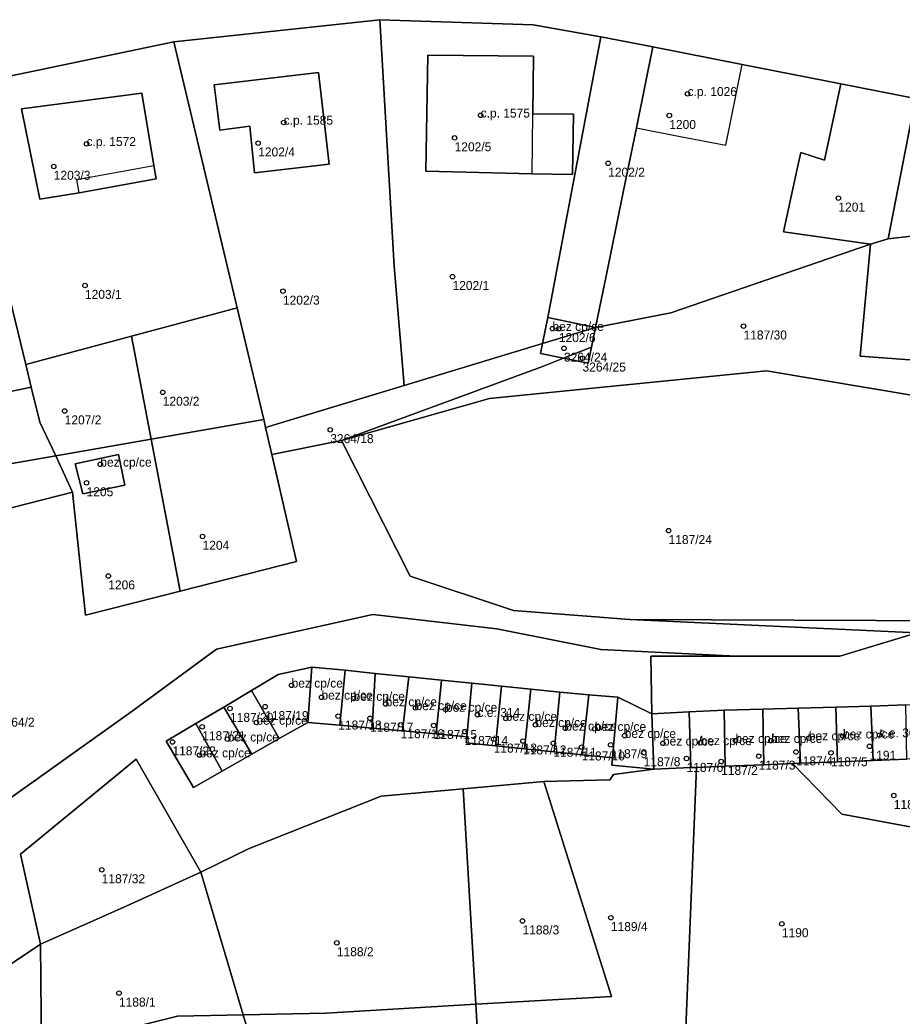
# Model space of a CAD drawing. Extents: x -878211 to -870363, y -1058464 to -1052522.
# Drawn here: x -875506.9 to -875408.6, y -1056330.6 to -1056219.6 of the extents above; entities that cross this region are included whole.
import ezdxf

# ---------------------------------------------------------------- set-up
doc = ezdxf.new("R2010")
doc.units = 0
for name, color, linetype in [('Definiční body', 7, 'Continuous'), ('Polygon budovy', 7, 'Continuous'), ('Polygon parcely', 7, 'Continuous')]:
    doc.layers.add(name, color=color, linetype=linetype)

msp = doc.modelspace()

# ---------------------------------------------------------------- linework, layer by layer
at = {"layer": 'Definiční body'}
for centre in [(-875432.53, -1056227.81994), (-875455.6, -1056230.21994), (-875434.57, -1056230.24994), (-875477.55, -1056231.01994), (-875458.5, -1056232.73994), (-875499.52, -1056233.39994), (-875480.39, -1056233.31994), (-875503.18, -1056235.91994), (-875441.38, -1056235.56994), (-875415.72, -1056239.45994), (-875458.73, -1056248.19994), (-875499.7, -1056249.18994), (-875477.63, -1056249.82994), (-875447.59, -1056253.99994), (-875446.88, -1056254.00994), (-875426.29, -1056253.71994), (-875446.31, -1056256.18994), (-875444.24, -1056257.28994), (-875491.03, -1056261.09994), (-875501.96, -1056263.17994), (-875472.36, -1056265.26994), (-875497.99, -1056269.12994), (-875499.52, -1056271.18994), (-875486.59, -1056277.15994), (-875434.65, -1056276.51994), (-875497.1, -1056281.56994), (-875476.67, -1056293.75994), (-875473.34, -1056295.09994), (-875469.76, -1056295.22994), (-875483.53, -1056296.33994), (-875479.61, -1056296.13994), (-875466.19, -1056295.83994), (-875462.86, -1056296.26994), (-875471.47, -1056297.18994), (-875467.93, -1056297.43994), (-875459.47, -1056296.44994), (-875455.95, -1056297.02994), (-875452.8, -1056297.45994), (-875486.63, -1056298.37994), (-875480.59, -1056297.89994), (-875464.51, -1056298.15994), (-875460.83, -1056298.23994), (-875449.49, -1056298.14994), (-875446.15, -1056298.54994), (-875457.37, -1056298.91994), (-875442.87, -1056298.59994), (-875439.54, -1056299.36994), (-875419.02, -1056299.63994), (-875415.21, -1056299.42994), (-875411.13, -1056299.29994), (-875489.95, -1056300.06994), (-875483.81, -1056299.75994), (-875454.15, -1056299.75994), (-875450.87, -1056299.96994), (-875447.49, -1056300.21994), (-875444.34, -1056300.63994), (-875441.1, -1056300.38994), (-875435.28, -1056300.21994), (-875431.09, -1056300.16994), (-875427.2, -1056299.92994), (-875423.23, -1056299.92994), (-875412.25, -1056300.55994), (-875486.94, -1056301.52994), (-875437.42, -1056301.27994), (-875432.65, -1056301.90994), (-875424.6, -1056301.65994), (-875420.44, -1056301.18994), (-875416.55, -1056301.27994), (-875428.79, -1056302.24994), (-875409.55, -1056306.03994), (-875497.83, -1056314.31994), (-875441.08, -1056319.65994), (-875450.93, -1056320.02994), (-875422.02, -1056320.33994), (-875471.62, -1056322.45994), (-875495.91, -1056328.06994)]:
    msp.add_circle(centre, 0.25, dxfattribs=at)
at = {"layer": 'Polygon budovy'}
for points in [[(-875436.42, -1056222.58), (-875438.21, -1056231.61), (-875433.35, -1056232.59), (-875428.26, -1056233.56), (-875426.44, -1056224.56)], [(-875461.48, -1056223.5), (-875461.69, -1056236.43), (-875449.85, -1056236.74), (-875449.78, -1056230.05), (-875449.69, -1056223.64)], [(-875473.68, -1056225.46), (-875485.3, -1056226.82), (-875484.66, -1056231.86), (-875481.33, -1056231.45), (-875480.82, -1056236.64), (-875472.49, -1056235.68)], [(-875493.38, -1056227.76), (-875506.77, -1056229.51), (-875504.74, -1056239.58), (-875500.36, -1056238.86), (-875500.61, -1056237.36), (-875492.01, -1056235.82)], [(-875448.94, -1056256.76), (-875446.37, -1056257.29), (-875443.61, -1056257.86), (-875443.23, -1056256.05), (-875442.78, -1056253.86), (-875448.11, -1056252.74), (-875448.71, -1056255.66)], [(-875495.98, -1056268.04), (-875500.78, -1056269.05), (-875499.95, -1056272.42), (-875495.27, -1056271.43)], [(-875478.16, -1056292.55), (-875481.15, -1056294.33), (-875478.04, -1056299.69), (-875474.86, -1056297.88), (-875474.42, -1056291.72)], [(-875474.42, -1056291.72), (-875474.86, -1056297.88), (-875471.31, -1056298.2), (-875470.69, -1056292.07)], [(-875467.67, -1056298.53), (-875467.34, -1056292.43), (-875470.69, -1056292.07), (-875471.31, -1056298.2)], [(-875467.67, -1056298.53), (-875464.31, -1056298.83), (-875463.59, -1056292.81), (-875467.34, -1056292.43)], [(-875464.31, -1056298.83), (-875460.57, -1056299.17), (-875459.97, -1056293.18), (-875463.59, -1056292.81)], [(-875460.57, -1056299.17), (-875457.15, -1056299.48), (-875456.58, -1056293.51), (-875459.97, -1056293.18)], [(-875457.15, -1056299.48), (-875457.21, -1056300.18), (-875453.95, -1056300.51), (-875453.27, -1056293.85), (-875456.58, -1056293.51)], [(-875453.27, -1056293.85), (-875453.95, -1056300.51), (-875450.69, -1056300.85), (-875450.02, -1056294.2)], [(-875481.15, -1056294.33), (-875484.23, -1056296.19), (-875481.1, -1056301.44), (-875478.04, -1056299.69)], [(-875450.02, -1056294.2), (-875450.69, -1056300.85), (-875447.42, -1056301.18), (-875446.78, -1056294.5)], [(-875446.78, -1056294.5), (-875447.42, -1056301.18), (-875444.28, -1056301.5), (-875443.54, -1056294.8)], [(-875444.28, -1056301.5), (-875440.9, -1056301.84), (-875440.3, -1056295.09), (-875443.54, -1056294.8)], [(-875440.98, -1056302.65), (-875436.29, -1056303.09), (-875436.52, -1056296.94), (-875440.3, -1056295.09), (-875440.9, -1056301.84)], [(-875412.12, -1056296.06), (-875416.02, -1056296.19), (-875415.81, -1056302.28), (-875411.83, -1056302.12)], [(-875408.21, -1056295.93), (-875412.12, -1056296.06), (-875411.83, -1056302.12), (-875408.09, -1056301.98)], [(-875484.23, -1056296.19), (-875487.35, -1056298.02), (-875484.41, -1056303.32), (-875481.1, -1056301.44)], [(-875432.35, -1056296.72), (-875436.52, -1056296.94), (-875436.29, -1056303.09), (-875432.16, -1056302.93)], [(-875428.45, -1056296.53), (-875432.35, -1056296.72), (-875432.16, -1056302.93), (-875431.52, -1056302.9), (-875428.34, -1056302.78)], [(-875424.13, -1056296.4), (-875428.45, -1056296.53), (-875428.34, -1056302.78), (-875424.03, -1056302.61)], [(-875420.2, -1056296.3), (-875424.13, -1056296.4), (-875424.03, -1056302.61), (-875420.85, -1056302.48), (-875419.95, -1056302.44)], [(-875416.02, -1056296.19), (-875420.2, -1056296.3), (-875419.95, -1056302.44), (-875415.81, -1056302.28)], [(-875487.35, -1056298.02), (-875490.64, -1056299.99), (-875487.59, -1056305.13), (-875484.41, -1056303.32)]]:
    msp.add_lwpolyline(points, close=True, dxfattribs=at)
at = {"layer": 'Polygon parcely'}
for points in [[(-875611.38, -1056250.03), (-875591.34, -1056245.14), (-875577.58, -1056242.07), (-875562.16, -1056239.29), (-875547.53, -1056235.13), (-875540.74, -1056233.15), (-875537.65, -1056232.55), (-875513.82, -1056227.05), (-875489.8, -1056222.05), (-875466.82, -1056219.59), (-875449.74, -1056220.14), (-875442.2, -1056221.48), (-875436.42, -1056222.58), (-875426.44, -1056224.56), (-875415.46, -1056226.72), (-875407.14, -1056228.36)], [(-875509.54, -1056307.36), (-875494.44, -1056296.62), (-875485.04, -1056289.72), (-875467.61, -1056285.87), (-875453.79, -1056287.46), (-875442.19, -1056289.75), (-875427.13, -1056290.52), (-875415.57, -1056290.51), (-875406.97, -1056287.91), (-875438.96, -1056286.41), (-875451.95, -1056285.4), (-875463.46, -1056281.58), (-875467.91, -1056272.8), (-875471.12, -1056266.48), (-875478.86, -1056268.03), (-875476.11, -1056279.94), (-875489.08, -1056283.25), (-875499.63, -1056285.94), (-875501.1, -1056272.24), (-875519.13, -1056276.83)], [(-875521.41, -1056333.83), (-875504.67, -1056322.59), (-875506.9, -1056312.58), (-875494.01, -1056301.99), (-875486.78, -1056314.58), (-875481.41, -1056311.93), (-875466.7, -1056306.12), (-875457.54, -1056305.3), (-875448.56, -1056304.49), (-875441.2, -1056304.28), (-875440.8, -1056303.7), (-875436.29, -1056303.09), (-875440.98, -1056302.65), (-875440.9, -1056301.84), (-875444.28, -1056301.5), (-875447.42, -1056301.18), (-875450.69, -1056300.85), (-875453.95, -1056300.51), (-875457.21, -1056300.18), (-875457.15, -1056299.48), (-875460.57, -1056299.17), (-875464.31, -1056298.83), (-875467.67, -1056298.53), (-875471.31, -1056298.2), (-875474.86, -1056297.88), (-875478.04, -1056299.69), (-875481.1, -1056301.44), (-875484.41, -1056303.32), (-875487.59, -1056305.13), (-875490.64, -1056299.99), (-875487.35, -1056298.02), (-875484.23, -1056296.19), (-875481.15, -1056294.33), (-875478.16, -1056292.55), (-875474.42, -1056291.72), (-875470.69, -1056292.07), (-875467.34, -1056292.43), (-875463.59, -1056292.81), (-875459.97, -1056293.18), (-875456.58, -1056293.51), (-875453.27, -1056293.85), (-875450.02, -1056294.2), (-875446.78, -1056294.5), (-875443.54, -1056294.8), (-875440.3, -1056295.09), (-875436.52, -1056296.94), (-875436.64, -1056290.52), (-875427.13, -1056290.52), (-875442.19, -1056289.75), (-875453.79, -1056287.46), (-875467.61, -1056285.87), (-875485.04, -1056289.72), (-875494.44, -1056296.62), (-875509.54, -1056307.36)]]:
    msp.add_lwpolyline(points, dxfattribs=at)
for points in [[(-875466.82, -1056219.59), (-875489.8, -1056222.05), (-875482.73, -1056251.69), (-875479.76, -1056264.14), (-875479.56, -1056265.02), (-875464.13, -1056260.34), (-875465.22, -1056247.05)], [(-875449.74, -1056220.14), (-875466.82, -1056219.59), (-875465.22, -1056247.05), (-875464.13, -1056260.34), (-875448.71, -1056255.66), (-875448.11, -1056252.74), (-875442.2, -1056221.48)], [(-875442.78, -1056253.86), (-875441.71, -1056248.68), (-875441.1, -1056245.6), (-875439.71, -1056238.79), (-875438.21, -1056231.61), (-875436.42, -1056222.58), (-875442.2, -1056221.48), (-875448.11, -1056252.74)], [(-875506.3, -1056258), (-875494.52, -1056254.85), (-875482.73, -1056251.69), (-875489.8, -1056222.05), (-875513.82, -1056227.05)], [(-875436.42, -1056222.58), (-875438.21, -1056231.61), (-875439.71, -1056238.79), (-875441.1, -1056245.6), (-875441.71, -1056248.68), (-875442.78, -1056253.86), (-875434.41, -1056252.24), (-875412.13, -1056244.58), (-875421.83, -1056243.21), (-875420.25, -1056235.85), (-875419.92, -1056234.36), (-875417.28, -1056235.22), (-875415.46, -1056226.72), (-875426.44, -1056224.56)], [(-875445.25, -1056230.11), (-875449.78, -1056230.05), (-875449.69, -1056223.64), (-875461.48, -1056223.5), (-875461.69, -1056236.43), (-875449.85, -1056236.74), (-875445.34, -1056236.82)], [(-875445.25, -1056230.11), (-875445.34, -1056236.82), (-875449.85, -1056236.74), (-875461.69, -1056236.43), (-875461.48, -1056223.5), (-875449.69, -1056223.64), (-875449.78, -1056230.05)], [(-875481.33, -1056231.45), (-875480.82, -1056236.64), (-875472.49, -1056235.68), (-875473.68, -1056225.46), (-875485.3, -1056226.82), (-875484.66, -1056231.86)], [(-875481.33, -1056231.45), (-875484.66, -1056231.86), (-875485.3, -1056226.82), (-875473.68, -1056225.46), (-875472.49, -1056235.68), (-875480.82, -1056236.64)], [(-875506.3, -1056258), (-875513.82, -1056227.05), (-875537.65, -1056232.55), (-875533.04, -1056249.41), (-875532.94, -1056249.39), (-875536.29, -1056235.81), (-875526.24, -1056233.49), (-875525.61, -1056236.17), (-875523.04, -1056247.06), (-875532.75, -1056249.33), (-875531.19, -1056254.59), (-875531.52, -1056254.69), (-875528.65, -1056265.31), (-875505.68, -1056260.52)], [(-875415.46, -1056226.72), (-875417.28, -1056235.22), (-875419.92, -1056234.36), (-875420.25, -1056235.85), (-875421.83, -1056243.21), (-875412.13, -1056244.58), (-875410.18, -1056244), (-875407.14, -1056228.36)], [(-875500.36, -1056238.86), (-875491.76, -1056237.29), (-875492.01, -1056235.82), (-875493.38, -1056227.76), (-875506.77, -1056229.51), (-875504.74, -1056239.58)], [(-875500.36, -1056238.86), (-875504.74, -1056239.58), (-875506.77, -1056229.51), (-875493.38, -1056227.76), (-875492.01, -1056235.82), (-875491.76, -1056237.29)], [(-875392.29, -1056241.93), (-875390.52, -1056233.36), (-875390.16, -1056231.64), (-875407.14, -1056228.36), (-875410.18, -1056244)], [(-875381.72, -1056233.32), (-875383.35, -1056241.37), (-875383.81, -1056243.65), (-875386.56, -1056243.09), (-875392.29, -1056241.93), (-875410.18, -1056244), (-875412.13, -1056244.58), (-875413.29, -1056257.08), (-875402.24, -1056257.89), (-875401.83, -1056253.97), (-875395.92, -1056254.53), (-875396.34, -1056258.51), (-875381.73, -1056259.45), (-875373.92, -1056234.86)], [(-875471.12, -1056266.48), (-875454.6, -1056261.79), (-875423.74, -1056258.7), (-875395.61, -1056263.42), (-875385.95, -1056267.35), (-875386.1, -1056272.7), (-875381.73, -1056259.45), (-875396.34, -1056258.51), (-875402.24, -1056257.89), (-875413.29, -1056257.08), (-875412.13, -1056244.58), (-875434.41, -1056252.24), (-875442.78, -1056253.86), (-875443.23, -1056256.05), (-875443.61, -1056257.86), (-875446.37, -1056257.29), (-875448.58, -1056258.17)], [(-875492.32, -1056266.32), (-875479.76, -1056264.14), (-875482.73, -1056251.69), (-875494.52, -1056254.85)], [(-875442.78, -1056253.86), (-875448.11, -1056252.74), (-875448.71, -1056255.66)], [(-875443.23, -1056256.05), (-875442.78, -1056253.86), (-875448.71, -1056255.66), (-875448.94, -1056256.76), (-875446.37, -1056257.29)], [(-875526.64, -1056273.08), (-875520.69, -1056271.27), (-875502.95, -1056268.17), (-875504.74, -1056264.41), (-875505.68, -1056260.52), (-875528.65, -1056265.31), (-875531.52, -1056254.69), (-875534.6, -1056255.61), (-875532.63, -1056264.23), (-875529.8, -1056273.48)], [(-875505.68, -1056260.52), (-875504.74, -1056264.41), (-875502.95, -1056268.17), (-875492.32, -1056266.32), (-875494.52, -1056254.85), (-875506.3, -1056258)], [(-875478.86, -1056268.03), (-875471.12, -1056266.48), (-875448.58, -1056258.17), (-875446.37, -1056257.29), (-875448.94, -1056256.76), (-875448.71, -1056255.66), (-875464.13, -1056260.34), (-875479.56, -1056265.02)], [(-875446.37, -1056257.29), (-875443.61, -1056257.86), (-875443.23, -1056256.05)], [(-875395.61, -1056263.42), (-875423.74, -1056258.7), (-875454.6, -1056261.79), (-875471.12, -1056266.48), (-875467.91, -1056272.8), (-875463.46, -1056281.58), (-875451.95, -1056285.4), (-875438.96, -1056286.41), (-875402.38, -1056286.56), (-875390.47, -1056273.64), (-875392.98, -1056269.66)], [(-875492.32, -1056266.32), (-875489.08, -1056283.25), (-875476.11, -1056279.94), (-875478.86, -1056268.03), (-875479.56, -1056265.02), (-875479.76, -1056264.14)], [(-875502.95, -1056268.17), (-875501.1, -1056272.24), (-875499.63, -1056285.94), (-875489.08, -1056283.25), (-875492.32, -1056266.32)], [(-875519.39, -1056275.83), (-875522.49, -1056276.71), (-875522.73, -1056275.56), (-875524.7, -1056276.1), (-875525.38, -1056273.71), (-875526.36, -1056273.99), (-875526.64, -1056273.08), (-875529.8, -1056273.48), (-875537.28, -1056275.95), (-875535.63, -1056281.06), (-875535, -1056283.13), (-875526.21, -1056281.22), (-875525.41, -1056281.05), (-875525.43, -1056278.43), (-875519.13, -1056276.83), (-875501.1, -1056272.24), (-875502.95, -1056268.17), (-875520.69, -1056271.27), (-875519.6, -1056274.64)], [(-875495.27, -1056271.43), (-875499.95, -1056272.42), (-875500.78, -1056269.05), (-875495.98, -1056268.04)], [(-875495.27, -1056271.43), (-875495.98, -1056268.04), (-875500.78, -1056269.05), (-875499.95, -1056272.42)], [(-875438.96, -1056286.41), (-875406.97, -1056287.91), (-875394.57, -1056286.98), (-875391.02, -1056285.88), (-875386.1, -1056272.7), (-875402.38, -1056286.56)], [(-875404.17, -1056295.75), (-875400.44, -1056295.61), (-875396.44, -1056295.47), (-875396.26, -1056301.51), (-875391.02, -1056285.88), (-875394.57, -1056286.98), (-875406.97, -1056287.91), (-875415.57, -1056290.51), (-875427.13, -1056290.52), (-875436.64, -1056290.52), (-875436.52, -1056296.94), (-875432.35, -1056296.72), (-875428.45, -1056296.53), (-875424.13, -1056296.4), (-875420.2, -1056296.3), (-875416.02, -1056296.19), (-875412.12, -1056296.06), (-875408.21, -1056295.93)], [(-875478.04, -1056299.69), (-875474.86, -1056297.88), (-875474.42, -1056291.72), (-875478.16, -1056292.55), (-875481.15, -1056294.33)], [(-875474.86, -1056297.88), (-875471.31, -1056298.2), (-875470.69, -1056292.07), (-875474.42, -1056291.72)], [(-875470.69, -1056292.07), (-875471.31, -1056298.2), (-875467.67, -1056298.53), (-875467.34, -1056292.43)], [(-875467.34, -1056292.43), (-875467.67, -1056298.53), (-875464.31, -1056298.83), (-875463.59, -1056292.81)], [(-875463.59, -1056292.81), (-875464.31, -1056298.83), (-875460.57, -1056299.17), (-875459.97, -1056293.18)], [(-875459.97, -1056293.18), (-875460.57, -1056299.17), (-875457.15, -1056299.48), (-875456.58, -1056293.51)], [(-875457.15, -1056299.48), (-875457.21, -1056300.18), (-875453.95, -1056300.51), (-875453.27, -1056293.85), (-875456.58, -1056293.51)], [(-875453.95, -1056300.51), (-875450.69, -1056300.85), (-875450.02, -1056294.2), (-875453.27, -1056293.85)], [(-875481.1, -1056301.44), (-875478.04, -1056299.69), (-875481.15, -1056294.33), (-875484.23, -1056296.19)], [(-875450.69, -1056300.85), (-875447.42, -1056301.18), (-875446.78, -1056294.5), (-875450.02, -1056294.2)], [(-875447.42, -1056301.18), (-875444.28, -1056301.5), (-875443.54, -1056294.8), (-875446.78, -1056294.5)], [(-875443.54, -1056294.8), (-875444.28, -1056301.5), (-875440.9, -1056301.84), (-875440.3, -1056295.09)], [(-875440.3, -1056295.09), (-875440.9, -1056301.84), (-875440.98, -1056302.65), (-875436.29, -1056303.09), (-875436.52, -1056296.94)], [(-875412.12, -1056296.06), (-875416.02, -1056296.19), (-875415.81, -1056302.28), (-875411.83, -1056302.12)], [(-875408.21, -1056295.93), (-875412.12, -1056296.06), (-875411.83, -1056302.12), (-875408.09, -1056301.98)], [(-875487.35, -1056298.02), (-875484.41, -1056303.32), (-875481.1, -1056301.44), (-875484.23, -1056296.19)], [(-875436.29, -1056303.09), (-875432.16, -1056302.93), (-875432.35, -1056296.72), (-875436.52, -1056296.94)], [(-875432.35, -1056296.72), (-875432.16, -1056302.93), (-875431.52, -1056302.9), (-875428.34, -1056302.78), (-875428.45, -1056296.53)], [(-875424.13, -1056296.4), (-875428.45, -1056296.53), (-875428.34, -1056302.78), (-875424.03, -1056302.61)], [(-875420.2, -1056296.3), (-875424.13, -1056296.4), (-875424.03, -1056302.61), (-875420.85, -1056302.48), (-875419.95, -1056302.44)], [(-875416.02, -1056296.19), (-875420.2, -1056296.3), (-875419.95, -1056302.44), (-875415.81, -1056302.28)], [(-875487.35, -1056298.02), (-875490.64, -1056299.99), (-875487.59, -1056305.13), (-875484.41, -1056303.32)], [(-875411.83, -1056302.12), (-875415.81, -1056302.28), (-875419.95, -1056302.44), (-875420.85, -1056302.48), (-875415.33, -1056308.13), (-875403.11, -1056310.38), (-875400.67, -1056314.05), (-875396.26, -1056301.51), (-875400.2, -1056301.67), (-875403.75, -1056301.81), (-875408.09, -1056301.98)], [(-875504.67, -1056322.59), (-875495.44, -1056318.53), (-875486.78, -1056314.58), (-875494.01, -1056301.99), (-875506.9, -1056312.58)], [(-875418.39, -1056347.04), (-875414.86, -1056347.4), (-875411.47, -1056347.74), (-875411.16, -1056348.42), (-875410.64, -1056347.42), (-875406.59, -1056333.71), (-875400.67, -1056314.05), (-875403.11, -1056310.38), (-875415.33, -1056308.13), (-875420.85, -1056302.48), (-875424.03, -1056302.61), (-875428.34, -1056302.78), (-875431.52, -1056302.9), (-875433.3, -1056345.53)], [(-875449.57, -1056343.88), (-875439.97, -1056344.85), (-875436.47, -1056345.21), (-875433.3, -1056345.53), (-875431.52, -1056302.9), (-875432.16, -1056302.93), (-875436.29, -1056303.09), (-875440.8, -1056303.7), (-875441.2, -1056304.28), (-875448.56, -1056304.49), (-875441.02, -1056328.43), (-875456.13, -1056329.31), (-875455.26, -1056344.25)], [(-875441.02, -1056328.43), (-875448.56, -1056304.49), (-875457.54, -1056305.3), (-875456.13, -1056329.31)], [(-875456.13, -1056329.31), (-875457.54, -1056305.3), (-875466.7, -1056306.12), (-875481.41, -1056311.93), (-875486.78, -1056314.58), (-875482.06, -1056330.48), (-875472.81, -1056330.29)], [(-875504.67, -1056322.59), (-875504.56, -1056334.43), (-875489.37, -1056330.63), (-875482.06, -1056330.48), (-875486.78, -1056314.58), (-875495.44, -1056318.53)], [(-875565.35, -1056373.86), (-875555.26, -1056383.73), (-875541.31, -1056375.12), (-875531.82, -1056371.99), (-875520.61, -1056369.18), (-875525.82, -1056349.47), (-875501.96, -1056342.97), (-875503.24, -1056337.88), (-875504.56, -1056334.43), (-875504.67, -1056322.59), (-875521.41, -1056333.83), (-875540.21, -1056349.03)], [(-875478.72, -1056339.14), (-875474.96, -1056338.03), (-875472.87, -1056345.69), (-875472.64, -1056346.14), (-875472.33, -1056345.99), (-875469.56, -1056345.17), (-875460.75, -1056344.6), (-875457.31, -1056344.38), (-875455.26, -1056344.25), (-875456.13, -1056329.31), (-875472.81, -1056330.29), (-875482.06, -1056330.48), (-875479.42, -1056339.35)], [(-875477.91, -1056347.65), (-875477.65, -1056346.14), (-875477.86, -1056344.63), (-875479.42, -1056339.35), (-875482.06, -1056330.48), (-875489.37, -1056330.63), (-875504.56, -1056334.43), (-875503.24, -1056337.88), (-875501.96, -1056342.97), (-875498.26, -1056353.69), (-875482.41, -1056348.99), (-875478.17, -1056347.73)]]:
    msp.add_lwpolyline(points, close=True, dxfattribs=at)

# ---------------------------------------------------------------- texts
at = {"layer": 'Definiční body'}
for s, p in [('c.p. 1026', (-875432.53, -1056228.07)), ('c.p. 1575', (-875455.6, -1056230.47)), ('c.p. 1585', (-875477.55, -1056231.27)), ('1200', (-875434.57, -1056231.739)), ('c.p. 1572', (-875499.52, -1056233.649)), ('1202/4', (-875480.39, -1056234.809)), ('1202/5', (-875458.5, -1056234.229)), ('1202/2', (-875441.38, -1056237.059)), ('1203/3', (-875503.18, -1056237.409)), ('1201', (-875415.72, -1056240.949)), ('1202/1', (-875458.73, -1056249.689)), ('1203/1', (-875499.7, -1056250.679)), ('1202/3', (-875477.63, -1056251.319)), ('bez cp/ce', (-875447.59, -1056254.25)), ('1202/6', (-875446.88, -1056255.499)), ('1187/30', (-875426.29, -1056255.209)), ('3264/24', (-875446.31, -1056257.679)), ('3264/25', (-875444.24, -1056258.779)), ('1203/2', (-875491.03, -1056262.589)), ('1207/2', (-875501.96, -1056264.669)), ('3264/18', (-875472.36, -1056266.759)), ('bez cp/ce', (-875497.99, -1056269.379)), ('1205', (-875499.52, -1056272.679)), ('1187/24', (-875434.65, -1056278.009)), ('1204', (-875486.59, -1056278.649)), ('1206', (-875497.1, -1056283.059)), ('bez cp/ce', (-875476.67, -1056294.01)), ('bez cp/ce', (-875473.34, -1056295.35)), ('bez cp/ce', (-875469.76, -1056295.48)), ('bez cp/ce', (-875466.19, -1056296.09)), ('bez cp/ce', (-875462.86, -1056296.52)), ('bez cp/ce', (-875459.47, -1056296.7)), ('1187/20', (-875483.53, -1056297.829)), ('bez cp/ce', (-875480.59, -1056298.149)), ('1187/19', (-875479.61, -1056297.629)), ('c.e. 314', (-875455.95, -1056297.28)), ('bez cp/ce', (-875452.8, -1056297.71)), ('3264/2', (-875509.4, -1056298.359)), ('1187/18', (-875471.47, -1056298.679)), ('1187/17', (-875467.93, -1056298.929)), ('bez cp/ce', (-875449.49, -1056298.399)), ('bez cp/ce', (-875446.15, -1056298.8)), ('bez cp/ce', (-875442.87, -1056298.85)), ('1187/21', (-875486.63, -1056299.869)), ('bez cp/ce', (-875483.81, -1056300.01)), ('1187/16', (-875464.51, -1056299.649)), ('1187/15', (-875460.83, -1056299.729)), ('1187/14', (-875457.37, -1056300.409)), ('bez cp/ce', (-875439.54, -1056299.62)), ('bez cp/ce', (-875435.28, -1056300.47)), ('bez cp/ce', (-875431.09, -1056300.419)), ('bez cp/ce', (-875427.2, -1056300.179)), ('bez cp/ce', (-875423.23, -1056300.179)), ('bez cp/ce', (-875419.02, -1056299.889)), ('bez cp/ce', (-875415.21, -1056299.679)), ('c.e. 302', (-875411.13, -1056299.55)), ('1187/22', (-875489.95, -1056301.559)), ('1187/13', (-875454.15, -1056301.249)), ('1187/12', (-875450.87, -1056301.459)), ('bez cp/ce', (-875486.94, -1056301.78)), ('1187/11', (-875447.49, -1056301.709)), ('1187/10', (-875444.34, -1056302.129)), ('1187/9', (-875441.1, -1056301.879)), ('1187/4', (-875420.44, -1056302.679)), ('1191', (-875412.25, -1056302.049)), ('1187/8', (-875437.42, -1056302.769)), ('1187/6', (-875432.65, -1056303.399)), ('1187/2', (-875428.79, -1056303.739)), ('1187/3', (-875424.6, -1056303.149)), ('1187/5', (-875416.55, -1056302.769)), ('1187/29', (-875409.55, -1056307.529)), ('1187/32', (-875497.83, -1056315.809)), ('1188/3', (-875450.93, -1056321.519)), ('1189/4', (-875441.08, -1056321.149)), ('1190', (-875422.02, -1056321.829)), ('1188/2', (-875471.62, -1056323.949)), ('1188/1', (-875495.91, -1056329.559))]:
    msp.add_text(s, height=0.999996, dxfattribs=at).set_placement(p)

doc.saveas('drawing.dxf')
